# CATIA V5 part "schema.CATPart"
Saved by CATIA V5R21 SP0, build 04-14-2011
Part number: schema
Bounding box of the stored display mesh (mm): x -296.672 to 273.328, y -519.355 to 31.032, z 0 to 0
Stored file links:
  C:\Users\zerma\Pictures\CAO\schema.CATPart
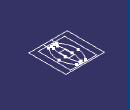
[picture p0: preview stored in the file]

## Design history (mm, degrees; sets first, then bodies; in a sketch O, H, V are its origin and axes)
Body1 (main body)
  Sketch1 on xy-plane, origin (0, 0, 0), H (1, 0, 0), V (0, 1, 0)
    spline S1 through (8.3019, -25.9104) (51.3615, -198.769) (31.3615, -398.769)
    spline S2 through (8.3019, -25.9104) (0, 0) (68.1926, -17.5097)
    spline S3 through (68.1926, -17.5097) (141.2522, -200.3684) (61.2522, -440.3684)
    spline S4 through (31.3615, -398.769) (20, -440) (61.2522, -440.3684)
    spline S5 through (-8.3019, -25.9104) (-51.3615, -198.769) (-31.3615, -398.769)
    spline S6 through (-8.3019, -25.9104) (0, 0) (-68.1926, -17.5097)
    spline S7 through (-68.1926, -17.5097) (-141.2522, -200.3684) (-61.2522, -440.3684)
    spline S8 through (-31.3615, -398.769) (-20, -440) (-61.2522, -440.3684)
    line L1 (-296.672, 31.0324) -> (273.328, 31.0324)
    line L2 (273.328, 31.0324) -> (273.328, -519.3548)
    line L3 (273.328, -519.3548) -> (-296.672, -519.3548)
    line L4 (-296.672, -519.3548) -> (-296.672, 31.0324)
    line L5 (-61.2522, -470) -> (61.2522, -470)
    line L6 (61.2522, -470) -> (61.2522, -519.3548)
    line L7 (61.2522, -519.3548) -> (-61.2522, -519.3548)
    line L8 (-61.2522, -519.3548) -> (-61.2522, -470)
    point P7 (61.2522, -519.3548)
    line L9 (-40, -160) -> (40, -160)
    line L10 (40, -160) -> (40, -300)
    line L11 (40, -300) -> (-40, -300)
    line L12 (-40, -300) -> (-40, -160)
    line L13 (-206.672, 10) -> (183.328, 10)
    line L14 (183.328, 10) -> (183.328, -470)
    line L15 (183.328, -470) -> (-206.672, -470)
    line L16 (-206.672, -470) -> (-206.672, 10)
    point P17 (8.3019, -25.9104)
    point P18 (8.3019, -25.9104)
    point P19 (0, 0)
    point P20 (31.3615, -398.769)
    point P21 (68.1926, -17.5097)
    point P22 (68.1926, -17.5097)
    point P23 (31.3615, -398.769)
    point P24 (20, -440)
    point P25 (61.2522, -440.3684)
    point P26 (61.2522, -440.3684)
    point P27 (-31.3615, -398.769)
    point P28 (-8.3019, -25.9104)
    point P29 (51.3615, -198.769)
    point P30 (-51.3615, -198.769)
    point P31 (-68.1926, -17.5097)
    point P32 (-8.3019, -25.9104)
    point P33 (0, 0)
    point P34 (-61.2522, -440.3684)
    point P35 (-68.1926, -17.5097)
    point P36 (141.2522, -200.3684)
    point P37 (-141.2522, -200.3684)
    point P38 (-61.2522, -440.3684)
    point P39 (-31.3615, -398.769)
    point P40 (-20, -440)
    distance L16 L4 = 90
    distance L14 L2 = 90
    coincidence: P18 P17, P19 O, P21 P22, P23 P20, P25 P26, P7 L3
    symmetry: S1 S5 V, S2 S6 V, S3 S7 V, S4 S8 V, P20 P27 V, P17 P28 V, P29 P30 V, P22 P31 V, P18 P32 V, P19 P33 V, P26 P34 V, P21 P35 V, P36 P37 V, P25 P38 V, P23 P39 V, P24 P40 V
    horizontal: L1 H, L3 H, L5 H, L7 H, L9 H, L11 H, L13 H, L15 H
    vertical: L2 V, L4 V, L6 V, L8 V, L10 V, L12 V, L14 V, L16 V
